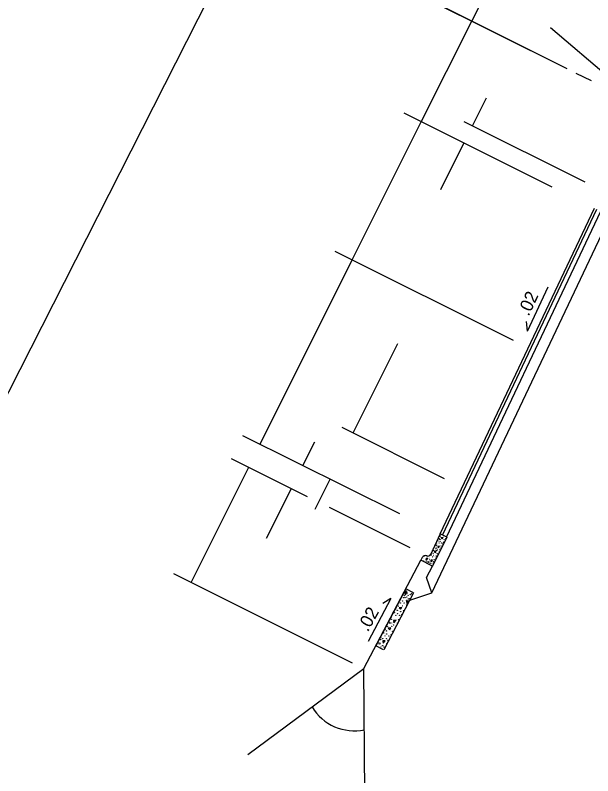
# Model space of a CAD drawing. Extents: x 1974386 to 1979988, y 776712 to 784860.
# Drawn here: x 1976485.2 to 1976754.2, y 781668.7 to 782023.3 of the extents above; entities that cross this region are included whole.
import ezdxf

# ---------------------------------------------------------------- set-up
doc = ezdxf.new("R2010")
doc.units = 0
for name, color, linetype in [('Default', 7, 'Continuous'), ('Old_Level_1', 7, 'Continuous'), ('Old_Level_2', 7, 'Continuous')]:
    doc.layers.add(name, color=color, linetype=linetype)

msp = doc.modelspace()

# ---------------------------------------------------------------- linework, layer by layer
at = {"layer": 'Default'}
msp.add_lwpolyline([(1978009.96, 784859.92), (1974385.88, 777715.09), (1976364.02, 776711.71), (1979988.11, 783856.54)], close=True, dxfattribs=at)
at = {"layer": 'Old_Level_1'}
for p, q in [((1976721.21, 782067.54), (1976697.76, 782020.56)), ((1976721.21, 782067.54), (1976697.76, 782020.56)), ((1976671.06, 782033.89), (1976742.15, 781998.41)), ((1976678.99, 782029.93), (1976742.15, 781998.41)), ((1976674.31, 781973.59), (1976697.76, 782020.56)), ((1976674.31, 781973.59), (1976697.76, 782020.56)), ((1976734.48, 782017.61), (1976777.4, 781980.81)), ((1976746.33, 781996.32), (1976753.4, 781992.79)), ((1976746.33, 781996.32), (1976753.4, 781992.79)), ((1976698.18, 781971.74), (1976704.7, 781984.81)), ((1976698.18, 781971.74), (1976704.7, 781984.81)), ((1976666.1, 781977.69), (1976735.11, 781943.25)), ((1976642.16, 781909.17), (1976674.31, 781973.59)), ((1976642.16, 781909.17), (1976674.31, 781973.59)), ((1976694.08, 781973.78), (1976750.5, 781945.62)), ((1976683.35, 781942.03), (1976694.16, 781963.69)), ((1976683.35, 781942.03), (1976694.16, 781963.69)), ((1976679.18, 781753.98), (1976770.6, 781947.16)), ((1976683.06, 781781.46), (1976754.94, 781933.35)), ((1976684.18, 781780.9), (1976756.06, 781932.79)), ((1976685.97, 781780.01), (1976757.85, 781931.9)), ((1976633.95, 781913.27), (1976717.16, 781871.74)), ((1976599.29, 781823.27), (1976642.16, 781909.17)), ((1976599.29, 781823.27), (1976642.16, 781909.17)), ((1976642.53, 781828.51), (1976663.34, 781870.22)), ((1976642.53, 781828.51), (1976663.34, 781870.22)), ((1976637.22, 781831.16), (1976684.98, 781807.32)), ((1976591.07, 781827.37), (1976664.1, 781790.92)), ((1976619.13, 781813.37), (1976624.67, 781824.46)), ((1976619.13, 781813.37), (1976624.67, 781824.46)), ((1976585.72, 781816.64), (1976621.15, 781798.95)), ((1976567.13, 781758.85), (1976593.93, 781812.54)), ((1976567.13, 781758.85), (1976593.93, 781812.54)), ((1976624.79, 781792.96), (1976631.81, 781807.04)), ((1976624.79, 781792.96), (1976631.81, 781807.04)), ((1976602.18, 781779.42), (1976613.77, 781802.63)), ((1976602.18, 781779.42), (1976613.77, 781802.63)), ((1976631.32, 781793.87), (1976668.91, 781775.11)), ((1976683.06, 781781.46), (1976678.69, 781771.95)), ((1976686.17, 781779.91), (1976679.47, 781766.49)), ((1976686.17, 781779.91), (1976683.06, 781781.46)), ((1976647.58, 781718.7), (1976674.11, 781769.17)), ((1976674.78, 781770.51), (1976674.11, 781769.17)), ((1976679.47, 781766.49), (1976674.11, 781769.17)), ((1976676.79, 781761.12), (1976679.47, 781766.49)), ((1976558.92, 781762.95), (1976642.11, 781721.43)), ((1976679.18, 781753.98), (1976676.79, 781761.12)), ((1976667.13, 781755.88), (1976653.13, 781729.25)), ((1976670.74, 781753.98), (1976667.13, 781755.88)), ((1976670.74, 781753.98), (1976656.78, 781727.42)), ((1976668.93, 781750.56), (1976679.18, 781753.98)), ((1976656.77, 781727.42), (1976653.17, 781729.32)), ((1976593.43, 781678.67), (1976647.58, 781718.7)), ((1976648.14, 781651.64), (1976647.58, 781718.7))]:
    msp.add_line(p, q, dxfattribs=at)
for centre, radius, start, end in [((1976676.12, 781769.84), 1.5, 66.2316, 153.4744), ((1976677.33, 781772.58), 1.5, 246.2316, 335.3029), ((1976643.11, 781712.63), 22.94, 210.9638, 281.8501)]:
    msp.add_arc(centre, radius, start, end, dxfattribs=at)
at = {"layer": 'Old_Level_2'}
for p, q in [((1976723.73, 781876), (1976733.33, 781896.59)), ((1976723.73, 781876), (1976723.34, 781880.44)), ((1976684.41, 781779.78), (1976683.57, 781779.64)), ((1976684.07, 781779.17), (1976684.41, 781779.78)), ((1976683.57, 781779.64), (1976684.07, 781779.17)), ((1976681.2, 781773.34), (1976680.36, 781773.21)), ((1976680.36, 781773.21), (1976680.86, 781772.74)), ((1976680.86, 781772.74), (1976681.2, 781773.34)), ((1976682.71, 781775.7), (1976681.96, 781775.67)), ((1976681.96, 781775.67), (1976682.08, 781774.95)), ((1976682.08, 781774.95), (1976682.71, 781775.7)), ((1976676.78, 781769.41), (1976676.94, 781770.32)), ((1976677.37, 781770), (1976676.78, 781769.41)), ((1976676.94, 781770.32), (1976677.37, 781770)), ((1976679.49, 781769.27), (1976678.74, 781769.24)), ((1976678.74, 781769.24), (1976678.86, 781768.51)), ((1976678.86, 781768.51), (1976679.49, 781769.27)), ((1976667.71, 781754.18), (1976666.58, 781754.16)), ((1976667.71, 781754.18), (1976666.58, 781754.16)), ((1976666.58, 781754.16), (1976666.74, 781753.07)), ((1976666.58, 781754.16), (1976666.74, 781753.07)), ((1976666.74, 781753.07), (1976667.71, 781754.18)), ((1976666.74, 781753.07), (1976667.71, 781754.18)), ((1976660.15, 781751.38), (1976649.58, 781731.27)), ((1976660.15, 781751.38), (1976656.38, 781749)), ((1976668.48, 781750.07), (1976667.35, 781750.05)), ((1976668.48, 781750.07), (1976667.35, 781750.05)), ((1976667.35, 781750.05), (1976667.51, 781748.97)), ((1976667.35, 781750.05), (1976667.51, 781748.97)), ((1976667.51, 781748.97), (1976668.48, 781750.07)), ((1976667.51, 781748.97), (1976668.48, 781750.07)), ((1976665.21, 781747.24), (1976663.94, 781747.07)), ((1976665.21, 781747.24), (1976663.94, 781747.07)), ((1976663.94, 781747.07), (1976664.67, 781746.35)), ((1976663.94, 781747.07), (1976664.67, 781746.35)), ((1976664.67, 781746.35), (1976665.21, 781747.24)), ((1976664.67, 781746.35), (1976665.21, 781747.24)), ((1976662.52, 781741.19), (1976661.39, 781741.17)), ((1976662.52, 781741.19), (1976661.39, 781741.17)), ((1976661.39, 781741.17), (1976661.55, 781740.08)), ((1976661.39, 781741.17), (1976661.55, 781740.08)), ((1976661.55, 781740.08), (1976662.52, 781741.19)), ((1976661.55, 781740.08), (1976662.52, 781741.19)), ((1976660.18, 781737.69), (1976658.92, 781737.51)), ((1976660.18, 781737.69), (1976658.92, 781737.51)), ((1976658.92, 781737.51), (1976659.65, 781736.79)), ((1976658.92, 781737.51), (1976659.65, 781736.79)), ((1976659.65, 781736.79), (1976660.18, 781737.69)), ((1976659.65, 781736.79), (1976660.18, 781737.69)), ((1976657.5, 781731.63), (1976656.37, 781731.61)), ((1976657.5, 781731.63), (1976656.37, 781731.61)), ((1976656.37, 781731.61), (1976656.53, 781730.52)), ((1976656.37, 781731.61), (1976656.53, 781730.52)), ((1976656.53, 781730.52), (1976657.5, 781731.63)), ((1976656.53, 781730.52), (1976657.5, 781731.63))]:
    msp.add_line(p, q, dxfattribs=at)
for centre, radius in [((1976682.65, 781780.14), 0.0462), ((1976683.1, 781780.83), 0.0462), ((1976683.29, 781780.12), 0.0462), ((1976684.64, 781780.25), 0.0462), ((1976681.33, 781776.76), 0.0462), ((1976681.84, 781778.16), 0.0462), ((1976682.14, 781778.12), 0.0462), ((1976682.59, 781779.22), 0.0462), ((1976682.63, 781777.25), 0.0462), ((1976683.04, 781778.81), 0.0462), ((1976683.1, 781777.82), 0.0462), ((1976683.81, 781777.25), 0.0462), ((1976684.25, 781776.66), 0.0462), ((1976684.54, 781777.62), 0.0462), ((1976684.95, 781778.74), 0.0462), ((1976685.72, 781779.38), 0.0462), ((1976679.38, 781772.78), 0.0462), ((1976679.89, 781774.4), 0.0462), ((1976680.08, 781773.68), 0.0462), ((1976680.78, 781775.01), 0.0462), ((1976680.81, 781774.64), 0.0462), ((1976681.28, 781776.01), 0.0462), ((1976681.32, 781774.85), 0.0462), ((1976681.43, 781773.81), 0.0462), ((1976681.91, 781774.19), 0.0462), ((1976682.5, 781772.94), 0.0462), ((1976682.93, 781774.09), 0.0462), ((1976683.24, 781774.93), 0.0462), ((1976683.47, 781775.91), 0.0462), ((1976675.33, 781769.98), 0.0462), ((1976675.72, 781771.19), 0.0462), ((1976676.41, 781769.78), 0.0462), ((1976676.95, 781771.23), 0.0462), ((1976678.07, 781769.57), 0.0462), ((1976678.11, 781770.32), 0.0462), ((1976678.63, 781771.72), 0.0462), ((1976678.93, 781771.68), 0.0462), ((1976679.42, 781770.81), 0.0462), ((1976679.83, 781772.37), 0.0462), ((1976679.89, 781771.38), 0.0462), ((1976680.26, 781769.47), 0.0462), ((1976680.59, 781770.81), 0.0462), ((1976681.04, 781770.22), 0.0462), ((1976681.33, 781771.18), 0.0462), ((1976681.74, 781772.3), 0.0462), ((1976675.22, 781768.87), 0.0462), ((1976676.63, 781768.82), 0.0462), ((1976676.68, 781767.96), 0.0462), ((1976677.57, 781768.57), 0.0462), ((1976677.6, 781768.2), 0.0462), ((1976678.11, 781768.41), 0.0462), ((1976678.22, 781767.37), 0.0462), ((1976678.7, 781767.75), 0.0462), ((1976679.29, 781766.51), 0.0462), ((1976679.71, 781767.65), 0.0462), ((1976680.02, 781768.49), 0.0462), ((1976666.02, 781751.76), 0.0693), ((1976666.02, 781751.76), 0.0693), ((1976666.37, 781752.64), 0.0693), ((1976666.37, 781752.64), 0.0693), ((1976666.69, 781751.75), 0.0693), ((1976666.69, 781751.75), 0.0693), ((1976666.7, 781754.55), 0.0693), ((1976666.7, 781754.55), 0.0693), ((1976667.31, 781754.85), 0.0693), ((1976667.31, 781754.85), 0.0693), ((1976667.5, 781752.11), 0.0693), ((1976667.5, 781752.11), 0.0693), ((1976667.76, 781753.99), 0.0693), ((1976667.76, 781753.99), 0.0693), ((1976668.14, 781752.9), 0.0693), ((1976668.14, 781752.9), 0.0693), ((1976668.84, 781751.35), 0.0693), ((1976668.84, 781751.35), 0.0693), ((1976669.19, 781753.19), 0.0693), ((1976669.19, 781753.19), 0.0693), ((1976669.75, 781753.62), 0.0693), ((1976669.75, 781753.62), 0.0693), ((1976664.51, 781749.3), 0.0693), ((1976664.51, 781749.3), 0.0693), ((1976665.52, 781750.17), 0.0693), ((1976665.52, 781750.17), 0.0693), ((1976665.57, 781747.94), 0.0693), ((1976665.57, 781747.94), 0.0693), ((1976666.31, 781749.31), 0.0693), ((1976666.31, 781749.31), 0.0693), ((1976667.33, 781748.27), 0.0693), ((1976667.33, 781748.27), 0.0693), ((1976667.46, 781750.44), 0.0693), ((1976667.46, 781750.44), 0.0693), ((1976668.26, 781751.09), 0.0693), ((1976668.26, 781751.09), 0.0693), ((1976661.3, 781744.89), 0.0693), ((1976661.3, 781744.89), 0.0693), ((1976661.75, 781744.82), 0.0693), ((1976661.75, 781744.82), 0.0693), ((1976662.46, 781746.46), 0.0693), ((1976662.46, 781746.46), 0.0693), ((1976663.12, 781745.83), 0.0693), ((1976663.12, 781745.83), 0.0693), ((1976663.18, 781744.35), 0.0693), ((1976663.18, 781744.35), 0.0693), ((1976663.54, 781747.78), 0.0693), ((1976663.54, 781747.78), 0.0693), ((1976664.72, 781745.2), 0.0693), ((1976664.72, 781745.2), 0.0693), ((1976665.99, 781745.66), 0.0693), ((1976665.99, 781745.66), 0.0693), ((1976660.39, 781741.69), 0.0693), ((1976660.39, 781741.69), 0.0693), ((1976660.48, 781742.81), 0.0693), ((1976660.48, 781742.81), 0.0693), ((1976662.46, 781743.5), 0.0693), ((1976662.46, 781743.5), 0.0693), ((1976663.67, 781741.47), 0.0693), ((1976663.67, 781741.47), 0.0693), ((1976664.22, 781743.47), 0.0693), ((1976664.22, 781743.47), 0.0693), ((1976665.33, 781744), 0.0693), ((1976665.33, 781744), 0.0693), ((1976658.52, 781738.23), 0.0693), ((1976658.52, 781738.23), 0.0693), ((1976659.61, 781740.21), 0.0693), ((1976659.61, 781740.21), 0.0693), ((1976659.64, 781739.64), 0.0693), ((1976659.64, 781739.64), 0.0693), ((1976660.42, 781739.95), 0.0693), ((1976660.42, 781739.95), 0.0693), ((1976660.55, 781738.39), 0.0693), ((1976660.55, 781738.39), 0.0693), ((1976661.28, 781738.94), 0.0693), ((1976661.28, 781738.94), 0.0693), ((1976663.29, 781740), 0.0693), ((1976663.29, 781740), 0.0693), ((1976656.28, 781735.34), 0.0693), ((1976656.28, 781735.34), 0.0693), ((1976656.73, 781735.27), 0.0693), ((1976656.73, 781735.27), 0.0693), ((1976657.43, 781736.9), 0.0693), ((1976657.43, 781736.9), 0.0693), ((1976657.43, 781733.95), 0.0693), ((1976657.43, 781733.95), 0.0693), ((1976658.1, 781736.27), 0.0693), ((1976658.1, 781736.27), 0.0693), ((1976658.16, 781734.79), 0.0693), ((1976658.16, 781734.79), 0.0693), ((1976659.2, 781733.91), 0.0693), ((1976659.2, 781733.91), 0.0693), ((1976660.31, 781734.44), 0.0693), ((1976660.31, 781734.44), 0.0693), ((1976660.96, 781736.11), 0.0693), ((1976660.96, 781736.11), 0.0693), ((1976654.59, 781730.65), 0.0693), ((1976654.59, 781730.65), 0.0693), ((1976654.62, 781730.09), 0.0693), ((1976654.62, 781730.09), 0.0693), ((1976655.37, 781732.14), 0.0693), ((1976655.37, 781732.14), 0.0693), ((1976655.4, 781730.39), 0.0693), ((1976655.4, 781730.39), 0.0693), ((1976655.46, 781733.26), 0.0693), ((1976655.46, 781733.26), 0.0693), ((1976656.33, 781732.65), 0.0693), ((1976656.33, 781732.65), 0.0693), ((1976658.11, 781732.62), 0.0693), ((1976658.11, 781732.62), 0.0693), ((1976658.27, 781730.45), 0.0693), ((1976658.27, 781730.45), 0.0693), ((1976658.65, 781731.92), 0.0693), ((1976658.65, 781731.92), 0.0693), ((1976655.53, 781728.83), 0.0693), ((1976655.53, 781728.83), 0.0693), ((1976656.26, 781729.38), 0.0693), ((1976656.26, 781729.38), 0.0693), ((1976656.97, 781728.73), 0.0693), ((1976656.97, 781728.73), 0.0693)]:
    msp.add_circle(centre, radius, dxfattribs=at)
msp.add_arc((1976679.43, 781773.7), 0.0462, 239.0866, 72.6376, dxfattribs=at)

# ---------------------------------------------------------------- texts
for rotation, p in [(64.666, (1976724.29, 781882.64)), (60.9734, (1976649.4, 781735.46))]:
    msp.add_text('.02 ', height=6, rotation=rotation, dxfattribs=at).set_placement(p)

doc.saveas('drawing.dxf')
